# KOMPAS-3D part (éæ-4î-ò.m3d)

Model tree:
1. Объединить компоненты:1
2. Эскиз:2
3. Операция выдавливания:1
     Расстояние 1 = 8
4. Скругление:1
     Радиус = 10

Referenced files in D:\Работа\Мещеряков\Сигнализатор ВС\Черновики\: ВС-4М (.070, .071-00, .071-01).a3d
